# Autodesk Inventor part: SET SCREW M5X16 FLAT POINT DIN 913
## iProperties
Created: 2006-02
Part Number: SET SCREW M5X16 FLAT POINT DIN 913
Material: Steel, Mild
Description: Hexagon Socket Set Screw
Document SubType Name: Modeling
Standard: DIN 913
Designer: Andy Moles
Standards Organization: DIN
Language: en-US
Size Designation: M5 x 25
Categories: <MemberInstance><Categories><Category DisplayName="Fasteners" InternalName="e4da775c-781d-43d5-af7c-5136215cf5a6" Mnemonic="FSTN"><Category DisplayName="Bolts"
Density: 1 g/cm^3
Author: Andy Moles
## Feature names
1. Body [Revolution]
2. Slot [Extrusion]
3. Chamfer1
4. Chamfer2
